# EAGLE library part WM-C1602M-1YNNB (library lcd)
Display a cristalli liquidi tipo WM-C1602M WINTEK http://www.....
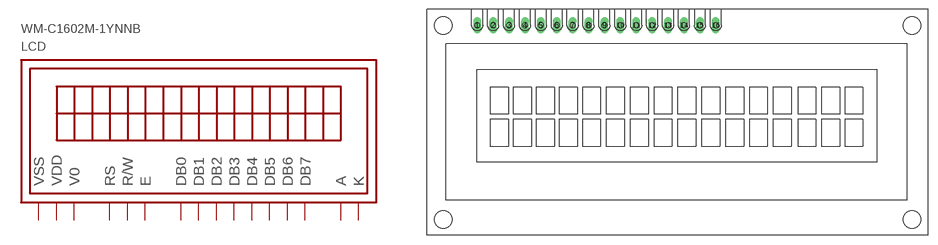
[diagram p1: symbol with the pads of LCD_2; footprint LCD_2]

Designator prefix LCD

## WM-C1602M-1YNNB  [LCD_2]
1  VSS
2  VDD
3  V0
4  RS
5  R/W
6  E
7  DB0
8  DB1
9  DB2
10  DB3
11  DB4
12  DB5
13  DB6
14  DB7
15  A
16  K

## Footprint LCD_2 (pad centres in mm)
Display a cristalli liquidi tipo WM-C1602M WINTEK Dimensioni: 80x36mm
drill 0.8 long: 1 0,0; 2 2.54,0; 3 5.08,0; 4 7.62,0; 5 10.16,0; 6 12.7,0; 7 15.24,0; 8 17.78,0; 9 20.32,0; 10 22.86,0; 11 25.4,0; 12 27.94,0; 13 30.48,0; 14 33.02,0; 15 35.56,0; 16 38.1,0
hole 2.8 at -5.461,0
hole 2.8 at -5.461,-30.988
hole 2.8 at 69.469,0
hole 2.8 at 69.469,-30.988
